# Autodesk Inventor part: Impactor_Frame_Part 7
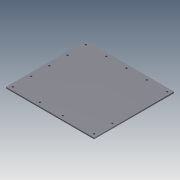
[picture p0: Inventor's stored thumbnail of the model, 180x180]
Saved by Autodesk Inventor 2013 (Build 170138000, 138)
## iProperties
Created: 2012-08
Part Number: Impactor_Frame_Part 7
Material: Steel, Mild
Document SubType Name: Modeling
Designer: mike.van voorhis
Density: 7.86 g/cm^3
Author: mike.van voorhis
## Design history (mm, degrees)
sketch "Sketch1"
  geometry: L1 (0, 0)-(644.525, 0); L2 (644.525, 0)-(644.525, 9.525); L3 (644.525, 9.525)-(0, 9.525); L4 (0, 9.525)-(0, 0)
  constraints: 8 end point, 2 parallel, 1 horizontal, 1 perpendicular
  dimensions: "d0" = 644.525 distance of L3.end L2.end; "d1" = 9.525 distance of L2.end L1.end
extrude "Extrusion1" new body sketch "Sketch1" distance "d2" = 584.2; taper "d3" = 0 deg
sketch "Sketch2"
  geometry: L1 (0, 0)-(0, 584.2) reference; L2 (644.525, 0)-(644.525, 584.2) reference; L3 (0, 25.4)-(25.4, 25.4); L4 (25.4, 25.4)-(25.4, 158.75); L5 (25.4, 158.75)-(25.4, 292.1); L6 (25.4, 292.1)-(25.4, 425.45); L7 (25.4, 425.45)-(25.4, 558.8); L8 (25.4, 25.4)-(222.25, 25.4); L9 (644.525, 25.4)-(619.125, 25.4); L10 (619.125, 25.4)-(390.525, 25.4); L11 (619.125, 25.4)-(619.125, 158.75); L12 (619.125, 158.75)-(619.125, 292.1); L13 (619.125, 292.1)-(619.125, 425.45); L14 (619.125, 425.45)-(619.125, 558.8); L15 (25.4, 558.8)-(173.831, 558.8); L16 (173.831, 558.8)-(322.262, 558.8); L17 (322.262, 558.8)-(470.694, 558.8); C1 r 6.747 at (25.4, 25.4); C2 r 6.747 at (25.4, 158.75); C3 r 6.747 at (25.4, 292.1); C4 r 6.747 at (25.4, 425.45); C5 r 6.747 at (25.4, 558.8); C6 r 6.747 at (619.125, 25.4); C7 r 6.747 at (390.525, 25.4); C8 r 6.747 at (222.25, 25.4); C9 r 6.747 at (619.125, 158.75); C10 r 6.747 at (619.125, 558.8); C11 r 6.747 at (173.831, 558.8); C12 r 6.747 at (322.262, 558.8); C13 r 6.747 at (470.694, 558.8)
  constraints: 30 end point, 13 centre point, 13 coincident, 10 collinear, 4 perpendicular, 2 point on line
  dimensions: "d4" = 25.4 distance of L3.start L3.end; "d5" = 25.4 distance of L1.start L3.start; "d6" = 13.49375 diameter of C1; "d7" = 133.35 distance of L4.start L4.end; "d8" = 133.35 distance of L4.end L5.end; "d9" = 133.35 distance of L5.end L6.end; "d11" = 133.35 distance of L6.end L7.end; "d16" = 196.85 distance of L4.start L8.end; "d17" = 13.49375 diameter of C2; "d18" = 13.49375 diameter of C3; "d19" = 13.49375 diameter of C4; "d20" = 13.49375 diameter of C5; "d21" = 25.4 distance of L9.start L9.end; "d22" = 25.4 distance of L2.start L9.start; "d23" = 13.49375 diameter of C6; "d24" = 228.6 distance of L10.start L10.end; "d25" = 13.49375 diameter of C7; "d26" = 13.49375 diameter of C8; "d27" = 133.35 distance of L10.start L11.end; "d28" = 133.35 distance of L11.end L12.end; "d29" = 133.35 distance of L12.end L13.end; "d30" = 133.35 distance of L13.end L14.end; "d31" = 13.49375 diameter of C9; "d32" = 13.49375 diameter of C10; "d33" = 148.43125 distance of L15.start L15.end; "d34" = 148.43125 distance of L15.end L16.end; "d35" = 148.43125 distance of L16.end L17.end; "d36" = 13.49375 diameter of C11; "d37" = 13.49375 diameter of C12; "d38" = 13.49375 diameter of C13
hole "Hole1" sketch "Sketch2" at (25.4, 25.4), (25.4, 158.75), (25.4, 292.1), (25.4, 425.45), (25.4, 558.8), (173.831, 558.8), (322.262, 558.8), (470.694, 558.8), (619.125, 558.8), (619.125, 158.75), (619.125, 25.4), (390.525, 25.4)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 diameter "d39" = 13.49375; stored, may be unused: countersink angle "d43" = 82 deg, drill point angle "d45" = 118 deg; dims "d40" = 19.05, "d41" = 9.525, "d42" = 6.35, "d44" = 25.4
body "Solid1"
